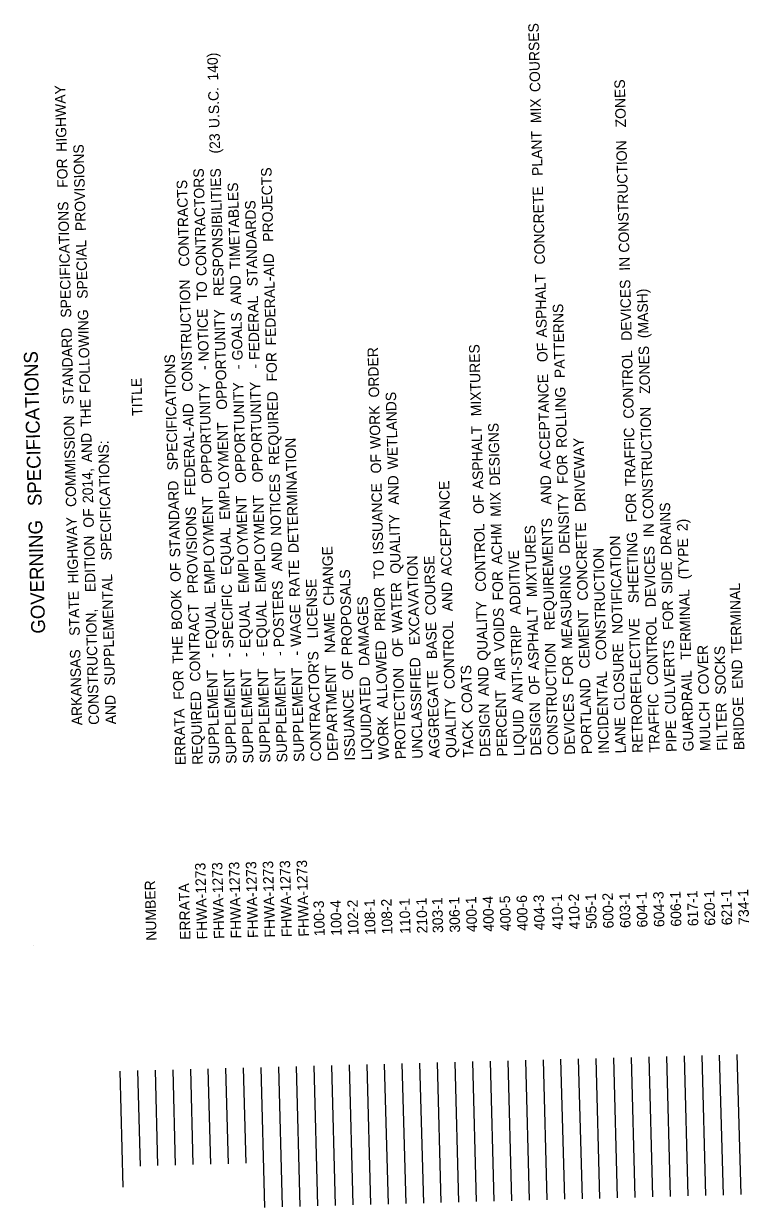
# Model space of a CAD drawing. Extents: x 1929542 to 1931706, y 595440 to 597808.
# Drawn here: x 1930907 to 1931307, y 595440 to 596094 of the extents above; entities that cross this region are included whole.
import ezdxf

# ---------------------------------------------------------------- set-up
doc = ezdxf.new("R2010")
doc.units = 0
doc.layers.add('Default', color=7, linetype='Continuous')
doc.layers.add('R_Annotation', color=7, linetype='Continuous')

msp = doc.modelspace()

# ---------------------------------------------------------------- linework, layer by layer
at = {"layer": 'Default'}
for p, q in [((1931301.35, 595524.52), (1931303.43, 595447.2)), ((1931057.69, 595517.98), (1931059.76, 595440.66)), ((1931067.43, 595518.24), (1931069.51, 595440.92)), ((1931077.18, 595518.5), (1931079.26, 595441.18)), ((1931086.93, 595518.77), (1931089, 595441.44)), ((1931096.67, 595519.03), (1931098.75, 595441.7)), ((1931106.42, 595519.29), (1931108.5, 595441.97)), ((1931116.17, 595519.55), (1931118.24, 595442.23)), ((1931125.91, 595519.81), (1931127.99, 595442.49)), ((1931135.66, 595520.07), (1931137.73, 595442.75)), ((1931145.41, 595520.33), (1931147.48, 595443.01)), ((1931155.15, 595520.6), (1931157.23, 595443.27)), ((1931164.9, 595520.86), (1931166.97, 595443.53)), ((1931174.65, 595521.12), (1931176.72, 595443.8)), ((1931184.39, 595521.38), (1931186.47, 595444.06)), ((1931194.14, 595521.64), (1931196.21, 595444.32)), ((1931203.88, 595521.9), (1931205.96, 595444.58)), ((1931213.63, 595522.17), (1931215.71, 595444.84)), ((1931223.38, 595522.43), (1931225.45, 595445.1)), ((1931233.12, 595522.69), (1931235.2, 595445.37)), ((1931242.87, 595522.95), (1931244.95, 595445.63)), ((1931252.62, 595523.21), (1931254.69, 595445.89)), ((1931262.36, 595523.47), (1931264.44, 595446.15)), ((1931272.11, 595523.74), (1931274.19, 595446.41)), ((1931281.86, 595524), (1931283.93, 595446.67)), ((1931291.6, 595524.26), (1931293.68, 595446.94)), ((1930960.22, 595515.36), (1930961.95, 595451.19)), ((1930969.97, 595515.63), (1930971.38, 595462.93)), ((1930979.72, 595515.89), (1930981.13, 595463.19)), ((1930989.46, 595516.15), (1930990.88, 595463.45)), ((1930999.21, 595516.41), (1931000.62, 595463.72)), ((1931008.95, 595516.67), (1931010.37, 595463.98)), ((1931018.7, 595516.93), (1931020.12, 595464.24)), ((1931028.45, 595517.2), (1931029.86, 595464.5)), ((1931038.19, 595517.46), (1931040.27, 595440.13)), ((1931047.94, 595517.72), (1931050.02, 595440.4))]:
    msp.add_line(p, q, dxfattribs=at)
at = {"layer": 'R_Annotation'}
msp.add_line((1930912.52, 595584.68), (1930912.52, 595584.68), dxfattribs=at)

# ---------------------------------------------------------------- texts
at = {"layer": 'Default'}
for s, height, p in [(' COURSES', 5.76, (1931192.77, 596054.16)), (' 140)', 5.76, (1931014.7, 596060.51)), (' ZONES', 5.76, (1931240.11, 596034.63)), (' HIGHWAY', 5.76, (1930931.01, 596021.17)), (' U.S.C.', 5.76, (1931015.4, 596034.24)), (' MIX', 5.76, (1931193.23, 596036.99)), (' PLANT', 5.76, (1931194.01, 596007.82)), (' (23', 5.76, (1931015.78, 596020.19)), (' CONSTRUCTION', 5.76, (1931241.97, 595965.47)), (' PROVISIONS', 5.76, (1930941.55, 595977.38)), (' FOR', 5.76, (1930931.55, 596001.26)), (' CONTRACTORS', 5.76, (1931008.23, 595952.54)), (' RESPONSIBILITIES', 5.76, (1931017.89, 595941.45)), (' PROJECTS', 5.76, (1931045.18, 595971.46)), (' CONTRACTS', 5.76, (1930998.73, 595957.73)), (' TIMETABLES', 5.76, (1931026.86, 595956.25)), (' CONCRETE', 5.76, (1931195.33, 595958.91)), (' SPECIFICATIONS', 5.76, (1930933.47, 595929.52)), (' STANDARDS', 5.76, (1931036.47, 595946.85)), (' SPECIAL', 5.76, (1930942.56, 595939.95)), (' FEDERAL-AID', 5.76, (1931046.71, 595914.17)), (' IN', 5.76, (1931242.24, 595955.45)), (' CONSTRUCTION', 5.76, (1931000.58, 595888.58)), (' TO', 5.76, (1931008.6, 595938.95)), (' AND', 5.76, (1931027.38, 595936.68)), (' ASPHALT', 5.76, (1931196.41, 595918.56)), (' DEVICES', 5.76, (1931243.28, 595916.77)), (' FEDERAL', 5.76, (1931037.57, 595906.16)), (' (MASH)', 5.76, (1931252.6, 595918.18)), (' NOTICE', 5.76, (1931009.5, 595905.41)), (' PATTERNS', 5.76, (1931206.38, 595896.15)), (' FOLLOWING', 5.76, (1930943.96, 595887.87)), (' OPPORTUNITY', 5.76, (1931019.58, 595878.65)), (' GOALS', 5.76, (1931028.21, 595905.91)), (' STANDARD', 5.76, (1930934.76, 595881.54)), (' OF', 5.76, (1931196.78, 595904.97)), (' SPECIFICATIONS', 7.68, (1930917.18, 595824.77)), (' SPECIFICATIONS', 5.76, (1930992.39, 595845.12)), (' FOR', 5.76, (1931047.25, 595894.26)), (' ORDER', 5.76, (1931103.67, 595885.43)), (' MIXTURES', 5.76, (1931160.12, 595875.08)), (' CONTROL', 5.76, (1931244.43, 595873.76)), (' ZONES', 5.76, (1931253.43, 595887.42)), (' -', 5.76, (1931009.63, 595900.55)), (' -', 5.76, (1931028.34, 595901.06)), (' -', 5.76, (1931037.7, 595901.31)), ('TITLE', 5.76, (1930972.79, 595877.46)), (' ACCEPTANCE', 5.76, (1931198.36, 595845.81)), (' OPPORTUNITY', 5.76, (1931011.31, 595837.75)), (' OPPORTUNITY', 5.76, (1931030.03, 595838.26)), (' OPPORTUNITY', 5.76, (1931039.38, 595838.51)), (' REQUIRED', 5.76, (1931048.49, 595848.14)), (' ROLLING', 5.76, (1931207.41, 595857.56)), (' THE', 5.76, (1930944.46, 595869.22)), (' WETLANDS', 5.76, (1931114.09, 595845.75)), (' FEDERAL-AID', 5.76, (1931002.12, 595831.28)), (' WORK', 5.76, (1931104.43, 595857.05)), (' CONSTRUCTION', 5.76, (1931255.28, 595818.26)), (' COMMISSION', 5.76, (1930936.28, 595824.96)), (' EMPLOYMENT', 5.76, (1931021.21, 595817.82)), (' ASPHALT', 5.76, (1931161.21, 595834.72)), (' DESIGNS', 5.76, (1931170.52, 595836.73)), (' AND', 5.76, (1930944.98, 595849.65)), (' DETERMINATION', 5.76, (1931059.16, 595799.46)), (' DRIVEWAY', 5.76, (1931217.73, 595822.15)), (' TRAFFIC', 5.76, (1931245.43, 595836.39)), (' SPECIFICATIONS:', 5.76, (1930955.8, 595795.4)), (' OF', 5.76, (1931104.79, 595843.47)), (' FOR', 5.76, (1931207.95, 595837.66)), (' 2014,', 5.76, (1930945.59, 595827.11)), (' NOTICES', 5.76, (1931049.54, 595809)), (' STANDARD', 5.76, (1930993.68, 595797.14)), (' ISSUANCE', 5.76, (1931105.99, 595798.74)), (' AND', 5.76, (1931114.62, 595826.18)), (' ACCEPTANCE', 5.76, (1931143.77, 595786.87)), (' AND', 5.76, (1931198.89, 595826.23)), (' EMPLOYMENT', 5.76, (1931012.95, 595776.92)), (' EMPLOYMENT', 5.76, (1931031.66, 595777.42)), (' EMPLOYMENT', 5.76, (1931041.02, 595777.68)), (' OF', 5.76, (1931161.57, 595821.14)), (' MIX', 5.76, (1931170.98, 595819.56)), (' DENSITY', 5.76, (1931208.98, 595799.07)), (' FOR', 5.76, (1931245.97, 595816.48)), (' OF', 5.76, (1930945.95, 595813.52)), (' PROVISIONS', 5.76, (1931003.57, 595777.23)), (' DRAINS', 5.76, (1931265.18, 595798.35)), ('GOVERNING', 7.68, (1930918.99, 595757.15)), (' HIGHWAY', 5.76, (1930937.42, 595782.65)), (' QUALITY', 5.76, (1931115.64, 595788.05)), (' REQUIREMENTS', 5.76, (1931200.75, 595756.82)), (' 2)', 5.76, (1931274.19, 595811.57)), (' EQUAL', 5.76, (1931022.03, 595787.38)), (' CONTROL', 5.76, (1931162.73, 595778.14)), (' ACHM', 5.76, (1931171.69, 595793.18)), (' MIXTURES', 5.76, (1931190.9, 595775.13)), (' CONCRETE', 5.76, (1931219.04, 595773.24)), (' SHEETING', 5.76, (1931247.17, 595771.84)), (' IN', 5.76, (1931255.55, 595808.24)), (' EDITION', 5.76, (1930946.91, 595777.89)), (' AND', 5.76, (1931050.06, 595789.43)), (' NOTIFICATION', 5.76, (1931238.26, 595754.84)), (' (TYPE', 5.76, (1931274.9, 595785.01)), (' CHANGE', 5.76, (1931078.66, 595770.4)), (' EXCAVATION', 5.76, (1931126.07, 595748.55)), (' COURSE', 5.76, (1931134.99, 595765.13)), (' ADDITIVE', 5.76, (1931181.79, 595765.51)), (' CONSTRUCTION', 5.76, (1931229.29, 595740.28)), (' DEVICES', 5.76, (1931256.59, 595769.56)), (' OF', 5.76, (1930994.04, 595783.56)), (' RATE', 5.76, (1931059.81, 595775.22)), (' TO', 5.76, (1931106.36, 595785.15)), (' MEASURING', 5.76, (1931210.39, 595746.51)), (' SIDE', 5.76, (1931265.76, 595776.91)), (' SUPPLEMENTAL', 5.76, (1930957.66, 595726.3)), (' POSTERS', 5.76, (1931051.19, 595747.48)), (' LICENSE', 5.76, (1931069.78, 595752.37)), (' PROPOSALS', 5.76, (1931088.76, 595742.97)), (' FOR', 5.76, (1931172.22, 595773.28)), (' STATE', 5.76, (1930938.19, 595753.76)), (' BOOK', 5.76, (1930994.75, 595757.03)), (' SPECIFIC', 5.76, (1931023.12, 595746.73)), (' PRIOR', 5.76, (1931107.13, 595756.4)), (' WATER', 5.76, (1931116.52, 595755.58)), (' AND', 5.76, (1931144.29, 595767.29)), (' TERMINAL', 5.76, (1931276.09, 595740.61)), (' TERMINAL', 5.76, (1931304.09, 595744.02)), (' CONTRACT', 5.76, (1931004.88, 595728.51)), (' EQUAL', 5.76, (1931013.76, 595746.48)), (' EQUAL', 5.76, (1931032.48, 595746.98)), (' EQUAL', 5.76, (1931041.83, 595747.23)), (' WAGE', 5.76, (1931060.55, 595747.74)), (' DAMAGES', 5.76, (1931098.29, 595737.08)), (' QUALITY', 5.76, (1931163.75, 595740.02)), (' FOR', 5.76, (1931266.29, 595757.01)), ('           CONSTRUCTION,', 5.76, (1930949.45, 595683.2)), (' NAME', 5.76, (1931079.36, 595744.31)), (' VOIDS', 5.76, (1931172.97, 595745.31)), (' ASPHALT', 5.76, (1931191.98, 595734.78)), (' CEMENT', 5.76, (1931220.05, 595735.69)), (' BASE', 5.76, (1931135.64, 595740.89)), (' CONTROL', 5.76, (1931145.45, 595724.29)), (' ANTI-STRIP', 5.76, (1931183.1, 595716.98)), ('RETROREFLECTIVE', 5.76, (1931249.33, 595691.25)), (' CONTROL', 5.76, (1931257.75, 595726.55)), (' THE', 5.76, (1930995.25, 595738.39)), (' OF', 5.76, (1931116.88, 595742)), (' CULVERTS', 5.76, (1931267.54, 595710.41)), ('           ARKANSAS', 5.76, (1930940.09, 595682.95)), (' -', 5.76, (1931041.96, 595742.38)), (' -', 5.76, (1931051.32, 595742.63)), (' -', 5.76, (1931060.68, 595742.88)), ("CONTRACTOR'S", 5.76, (1931071.55, 595686.48)), (' ALLOWED', 5.76, (1931108.28, 595713.54)), ('CONSTRUCTION', 5.76, (1931202.55, 595690)), (' CLOSURE', 5.76, (1931239.4, 595712.45)), (' COVER', 5.76, (1931285.97, 595721.38)), (' SOCKS', 5.76, (1931295.34, 595721.26)), (' -', 5.76, (1931013.89, 595741.62)), (' -', 5.76, (1931023.25, 595741.88)), (' -', 5.76, (1931032.61, 595742.13)), (' OF', 5.76, (1931089.13, 595729.38)), ('UNCLASSIFIED', 5.76, (1931127.69, 595687.99)), (' AIR', 5.76, (1931173.41, 595729.13)), (' FOR', 5.76, (1931210.93, 595726.61)), (' END', 5.76, (1931304.62, 595724.45)), (' FOR', 5.76, (1930995.79, 595718.48)), ('SUPPLEMENT', 5.76, (1931015.41, 595684.97)), ('SUPPLEMENT', 5.76, (1931024.77, 595685.23)), ('SUPPLEMENT', 5.76, (1931034.13, 595685.48)), ('SUPPLEMENT', 5.76, (1931043.48, 595685.73)), ('SUPPLEMENT', 5.76, (1931052.84, 595685.98)), ('SUPPLEMENT', 5.76, (1931062.2, 595686.23)), ('DEPARTMENT', 5.76, (1931080.91, 595686.73)), ('PROTECTION', 5.76, (1931118.34, 595687.74)), ('AGGREGATE', 5.76, (1931137.05, 595688.24)), (' COATS', 5.76, (1931155.16, 595711.08)), (' AND', 5.76, (1931164.28, 595720.44)), (' OF', 5.76, (1931192.35, 595721.19)), ('INCIDENTAL', 5.76, (1931230.62, 595690.75)), ('GUARDRAIL', 5.76, (1931277.4, 595692.01)), ('LIQUIDATED', 5.76, (1931099.62, 595687.24)), ('PORTLAND', 5.76, (1931221.26, 595690.5)), ('           AND', 5.76, (1930958.81, 595683.45)), ('REQUIRED', 5.76, (1931006.06, 595684.72)), ('ISSUANCE', 5.76, (1931090.27, 595686.98)), ('QUALITY', 5.76, (1931146.41, 595688.49)), ('PERCENT', 5.76, (1931174.48, 595689.24)), ('DEVICES', 5.76, (1931211.9, 595690.25)), ('TRAFFIC', 5.76, (1931258.69, 595691.5)), ('BRIDGE', 5.76, (1931305.47, 595692.76)), ('ERRATA', 5.76, (1930996.7, 595684.47)), ('DESIGN', 5.76, (1931165.12, 595688.99)), ('LIQUID', 5.76, (1931183.83, 595689.5)), ('DESIGN', 5.76, (1931193.19, 595689.75)), ('MULCH', 5.76, (1931286.76, 595692.26)), ('FILTER', 5.76, (1931296.11, 595692.51)), ('WORK', 5.76, (1931108.98, 595687.49)), ('TACK', 5.76, (1931155.76, 595688.74)), ('LANE', 5.76, (1931239.97, 595691)), ('PIPE', 5.76, (1931268.04, 595691.76)), ('FHWA-1273', 5.76, (1931008.65, 595588.23)), ('FHWA-1273', 5.76, (1931018, 595588.48)), ('FHWA-1273', 5.76, (1931027.36, 595588.74)), ('FHWA-1273', 5.76, (1931036.72, 595588.99)), ('FHWA-1273', 5.76, (1931046.07, 595589.24)), ('FHWA-1273', 5.76, (1931055.43, 595589.49)), ('FHWA-1273', 5.76, (1931064.79, 595589.74)), ('NUMBER', 5.76, (1930980.58, 595587.48)), ('ERRATA', 5.76, (1930999.29, 595587.98)), ('100-4', 5.76, (1931082.85, 595590.23)), ('102-2', 5.76, (1931092.21, 595590.48)), ('108-1', 5.76, (1931101.57, 595590.73)), ('108-2', 5.76, (1931110.92, 595590.98)), ('110-1', 5.76, (1931120.93, 595591.25)), ('210-1', 5.76, (1931130.28, 595591.5)), ('303-1', 5.76, (1931138.99, 595591.73)), ('306-1', 5.76, (1931148.35, 595591.98)), ('400-1', 5.76, (1931157.71, 595592.23)), ('400-4', 5.76, (1931167.06, 595592.49)), ('400-5', 5.76, (1931176.42, 595592.74)), ('400-6', 5.76, (1931185.78, 595592.99)), ('404-3', 5.76, (1931195.13, 595593.24)), ('410-1', 5.76, (1931205.14, 595593.51)), ('410-2', 5.76, (1931214.49, 595593.76)), ('505-1', 5.76, (1931223.85, 595594.01)), ('600-2', 5.76, (1931233.21, 595594.26)), ('603-1', 5.76, (1931242.56, 595594.51)), ('604-1', 5.76, (1931251.92, 595594.76)), ('604-3', 5.76, (1931261.28, 595595.01)), ('606-1', 5.76, (1931270.63, 595595.27)), ('617-1', 5.76, (1931279.99, 595595.52)), ('620-1', 5.76, (1931289.35, 595595.77)), ('621-1', 5.76, (1931298.7, 595596.02)), ('734-1', 5.76, (1931308.06, 595596.27)), ('100-3', 5.76, (1931073.5, 595589.97))]:
    msp.add_text(s, height=height, rotation=91.53769, dxfattribs=at).set_placement(p)

doc.saveas('drawing.dxf')
